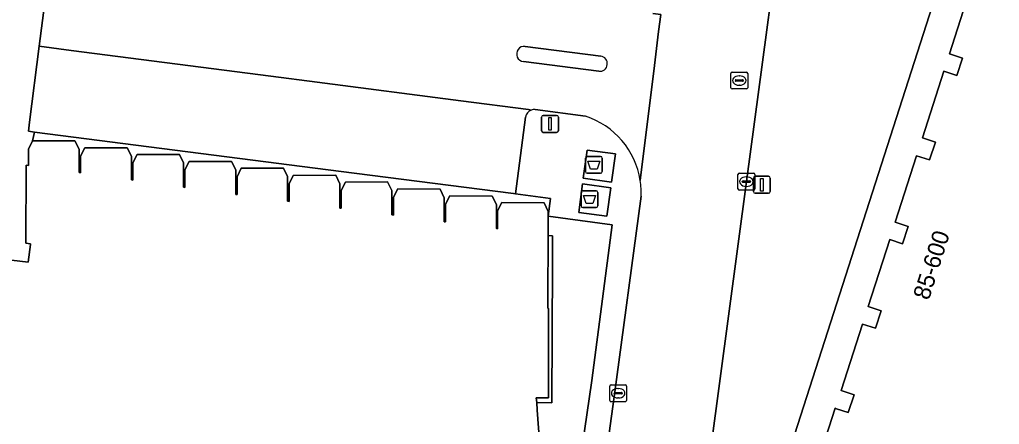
# Model space of a CAD drawing. Extents: x 160675 to 161153, y 383241 to 383714.
# Drawn here: x 160754 to 160812.1, y 383306.8 to 383330.8 of the extents above; entities that cross this region are included whole.
import ezdxf

# ---------------------------------------------------------------- set-up
doc = ezdxf.new("R2010")
doc.units = 0
for name, color, linetype in [('IMGEO_Afval_apart_plaats', 7, 'Continuous'), ('IMGEO_Groenvoorziening', 7, 'Continuous'), ('IMGEO_Kolk', 7, 'Continuous'), ('IMGEO_Lichtmast', 7, 'Continuous'), ('IMGEO_Muur', 7, 'Continuous'), ('IMGEO_Pand', 7, 'Continuous'), ('IMGEO_Pand_nummerreeks', 7, 'Continuous'), ('IMGEO_Parkeervlak_open', 7, 'Continuous'), ('IMGEO_Rijbaan_lokaal_open', 7, 'Continuous'), ('IMGEO_Rioolput', 7, 'Continuous'), ('IMGEO_Verkeerseiland_open', 7, 'Continuous'), ('IMGEO_Voetpad_gesloten', 7, 'Continuous'), ('IMGEO_Voetpad_open', 7, 'Continuous')]:
    doc.layers.add(name, color=color, linetype=linetype)

msp = doc.modelspace()

# ---------------------------------------------------------------- linework, layer by layer
at = {"layer": 'IMGEO_Afval_apart_plaats'}
for p, q in [((160787.535, 383321.83), (160787.535, 383322.63)), ((160787.535, 383322.63), (160787.535, 383321.83)), ((160787.635, 383322.73), (160788.425, 383322.73)), ((160788.425, 383322.73), (160787.635, 383322.73)), ((160788.525, 383322.63), (160788.525, 383321.83)), ((160788.525, 383321.83), (160788.525, 383322.63)), ((160788.425, 383321.73), (160787.635, 383321.73)), ((160787.635, 383321.73), (160788.425, 383321.73)), ((160787.375, 383320.7), (160788.165, 383320.7)), ((160788.165, 383320.7), (160787.375, 383320.7)), ((160787.275, 383319.8), (160787.275, 383320.6)), ((160787.275, 383320.6), (160787.275, 383319.8)), ((160788.265, 383320.6), (160788.265, 383319.8)), ((160788.265, 383319.8), (160788.265, 383320.6)), ((160788.165, 383319.7), (160787.375, 383319.7)), ((160787.375, 383319.7), (160788.165, 383319.7))]:
    msp.add_line(p, q, dxfattribs=at)
for points in [[(160787.678, 383322.444), (160788.382, 383322.444), (160788.233, 383321.974), (160787.827, 383321.974), (160787.678, 383322.444)], [(160787.418, 383320.414), (160788.122, 383320.414), (160787.973, 383319.944), (160787.567, 383319.944), (160787.418, 383320.414)]]:
    msp.add_lwpolyline(points, dxfattribs=at)
for centre, start, end in [((160787.635, 383322.63), 90, 180), ((160787.635, 383322.63), 90, 180), ((160788.425, 383322.63), 0, 90), ((160788.425, 383322.63), 360, 90), ((160787.635, 383321.83), 180, 270), ((160787.635, 383321.83), 180, 270), ((160788.425, 383321.83), 270, 0), ((160788.425, 383321.83), 270, 0), ((160787.375, 383320.6), 90, 180), ((160787.375, 383320.6), 90, 180), ((160788.165, 383320.6), 0, 90), ((160788.165, 383320.6), 360, 90), ((160787.375, 383319.8), 180, 270), ((160787.375, 383319.8), 180, 270), ((160788.165, 383319.8), 270, 0), ((160788.165, 383319.8), 270, 0)]:
    msp.add_arc(centre, 0.1, start, end, dxfattribs=at)
at = {"layer": 'IMGEO_Groenvoorziening'}
for points in [[(160800.391, 383345.424), (160799.695, 383340.873), (160797.071, 383321.237), (160794.447, 383301.572), (160793.115, 383291.71), (160793.033, 383291.064), (160794.963, 383290.783), (160811.629, 383342.72), (160809.925, 383343.284), (160810.812, 383346.001), (160808.782, 383346.694), (160804.384, 383348.108)], [(160786.2, 383297.65), (160787.903, 383309.445), (160789.121, 383318.677), (160785.331, 383319.191), (160785.325, 383318.048), (160785.577, 383318.015), (160785.576, 383317.889), (160785.57, 383316.389), (160785.536, 383308.126), (160784.642, 383308.13), (160784.675, 383307.69), (160784.931, 383304.271)]]:
    msp.add_lwpolyline(points, dxfattribs=at)
msp.add_lwpolyline([(160754.886, 383324.173), (160754.765, 383323.655), (160757.275, 383323.656), (160757.521, 383323.156), (160757.522, 383321.776), (160757.612, 383321.763), (160757.611, 383322.743), (160757.86, 383323.243), (160760.374, 383323.247), (160760.618, 383322.746), (160760.619, 383321.339), (160760.704, 383321.327), (160760.704, 383322.354), (160760.958, 383322.848), (160763.464, 383322.849), (160763.711, 383322.35), (160763.712, 383320.902), (160763.798, 383320.89), (160763.798, 383321.931), (160764.048, 383322.431), (160766.548, 383322.427), (160766.803, 383321.928), (160766.804, 383320.478), (160766.882, 383320.468), (160766.881, 383321.529), (160767.13, 383322.029), (160769.629, 383322.031), (160769.879, 383321.534), (160769.88, 383320.074), (160769.972, 383320.062), (160769.971, 383321.105), (160769.976, 383321.116), (160770.219, 383321.606), (160772.732, 383321.614), (160772.977, 383321.114), (160772.977, 383319.668), (160773.06, 383319.657), (160773.06, 383320.702), (160773.307, 383321.203), (160775.806, 383321.216), (160776.054, 383320.717), (160776.055, 383319.264), (160776.161, 383319.25), (160776.161, 383320.31), (160776.415, 383320.808), (160778.923, 383320.79), (160779.166, 383320.286), (160779.166, 383318.856), (160779.243, 383318.846), (160779.243, 383319.899), (160779.496, 383320.398), (160782.011, 383320.385), (160782.256, 383319.881), (160782.257, 383318.451), (160782.326, 383318.441), (160782.326, 383319.498), (160782.577, 383319.997), (160785.09, 383319.987), (160785.332, 383319.46), (160785.331, 383319.191), (160785.463, 383320.244), (160783.387, 383320.523), (160783.274, 383320.538), (160773.83, 383321.747)], close=True, dxfattribs=at)
at = {"layer": 'IMGEO_Kolk'}
for p, q in [((160796.57, 383320.811), (160796.57, 383321.663)), ((160796.645, 383321.737), (160797.497, 383321.737)), ((160796.872, 383321.28), (160797.27, 383321.28)), ((160797.058, 383321.517), (160797.083, 383321.517)), ((160797.571, 383321.663), (160797.571, 383320.811)), ((160797.497, 383320.737), (160796.645, 383320.737)), ((160796.829, 383321.231), (160796.829, 383321.243)), ((160797.267, 383321.194), (160796.869, 383321.194)), ((160797.081, 383320.957), (160797.056, 383320.957)), ((160797.313, 383321.243), (160797.313, 383321.231)), ((160788.972, 383308.261), (160788.972, 383309.113)), ((160789.047, 383309.187), (160789.899, 383309.187)), ((160789.973, 383309.113), (160789.973, 383308.261)), ((160789.231, 383308.681), (160789.231, 383308.693)), ((160789.669, 383308.644), (160789.271, 383308.644)), ((160789.274, 383308.73), (160789.672, 383308.73)), ((160789.46, 383308.967), (160789.485, 383308.967)), ((160789.715, 383308.693), (160789.715, 383308.681)), ((160789.899, 383308.187), (160789.047, 383308.187)), ((160789.483, 383308.407), (160789.458, 383308.407))]:
    msp.add_line(p, q, dxfattribs=at)
for points in [[(160796.57, 383320.811), (160796.57, 383321.663)], [(160796.645, 383321.737), (160797.497, 383321.737)], [(160797.571, 383321.663), (160797.571, 383320.811)], [(160797.497, 383320.737), (160796.645, 383320.737)], [(160788.972, 383308.261), (160788.972, 383309.113)], [(160789.047, 383309.187), (160789.899, 383309.187)], [(160789.973, 383309.113), (160789.973, 383308.261)], [(160789.899, 383308.187), (160789.047, 383308.187)]]:
    msp.add_lwpolyline(points, dxfattribs=at)
for centre, radius, start, end in [((160796.647, 383321.661), 0.0765, 91.55205, 178.44795), ((160796.647, 383321.661), 0.0765, 91.55205, 178.44795), ((160796.869, 383321.24), 0.0403, 85.87752, 175.75265), ((160797.274, 383321.242), 0.0386, 1.73085, 96.63898), ((160797.495, 383321.661), 0.0765, 1.55205, 88.44795), ((160797.495, 383321.661), 0.0765, 1.55205, 88.44795), ((160796.647, 383320.813), 0.0765, 181.55205, 268.44795), ((160796.647, 383320.813), 0.0765, 181.55205, 268.44795), ((160796.866, 383321.23), 0.0366, 178.93798, 274.71019), ((160797.27, 383321.237), 0.043, 264.86636, 352.45326), ((160797.495, 383320.813), 0.0765, 271.55205, 358.44795), ((160797.495, 383320.813), 0.0765, 271.55205, 358.44795), ((160789.049, 383309.111), 0.0765, 91.55205, 178.44795), ((160789.049, 383309.111), 0.0765, 91.55205, 178.44795), ((160789.897, 383309.111), 0.0765, 1.55205, 88.44795), ((160789.897, 383309.111), 0.0765, 1.55205, 88.44795), ((160789.271, 383308.69), 0.0403, 85.87752, 175.75265), ((160789.268, 383308.68), 0.0366, 178.93798, 274.71019), ((160789.672, 383308.687), 0.043, 264.86636, 352.45326), ((160789.676, 383308.692), 0.0386, 1.73085, 96.63898), ((160789.049, 383308.263), 0.0765, 181.55205, 268.44795), ((160789.049, 383308.263), 0.0765, 181.55205, 268.44795), ((160789.897, 383308.263), 0.0765, 271.55205, 358.44795), ((160789.897, 383308.263), 0.0765, 271.55205, 358.44795)]:
    msp.add_arc(centre, radius, start, end, dxfattribs=at)
for centre, major_axis, ratio, start_param, end_param in [((160797.057, 383321.237), (-0.387, 0.002), 0.722429, 4.712389, 7.853982), ((160797.082, 383321.237), (-0.39, 0.002), 0.717154, 1.570796, 4.712389), ((160789.459, 383308.687), (-0.387, 0.002), 0.722429, 4.712389, 7.853982), ((160789.484, 383308.687), (-0.39, 0.002), 0.717154, 1.570796, 4.712389)]:
    msp.add_ellipse(centre, major_axis=major_axis, ratio=ratio, start_param=start_param, end_param=end_param, dxfattribs=at)
at = {"layer": 'IMGEO_Lichtmast'}
for p, q in [((160784.935, 383324.26), (160784.935, 383325.06)), ((160784.935, 383325.06), (160784.935, 383324.26)), ((160785.035, 383325.16), (160785.825, 383325.16)), ((160785.825, 383325.16), (160785.035, 383325.16)), ((160785.925, 383325.06), (160785.925, 383324.26)), ((160785.925, 383324.26), (160785.925, 383325.06)), ((160785.825, 383324.16), (160785.035, 383324.16)), ((160785.035, 383324.16), (160785.825, 383324.16)), ((160797.491, 383320.653), (160797.491, 383321.453)), ((160797.491, 383321.453), (160797.491, 383320.653)), ((160797.591, 383321.553), (160798.381, 383321.553)), ((160798.381, 383321.553), (160797.591, 383321.553)), ((160798.481, 383321.453), (160798.481, 383320.653)), ((160798.481, 383320.653), (160798.481, 383321.453)), ((160798.381, 383320.553), (160797.591, 383320.553)), ((160797.591, 383320.553), (160798.381, 383320.553))]:
    msp.add_line(p, q, dxfattribs=at)
for points in [[(160785.355, 383325.035), (160785.505, 383325.035), (160785.505, 383324.285), (160785.355, 383324.285), (160785.355, 383325.035)], [(160797.911, 383321.428), (160798.061, 383321.428), (160798.061, 383320.678), (160797.911, 383320.678), (160797.911, 383321.428)]]:
    msp.add_lwpolyline(points, dxfattribs=at)
for centre, start, end in [((160785.035, 383325.06), 90, 180), ((160785.035, 383325.06), 90, 180), ((160785.825, 383325.06), 0, 90), ((160785.825, 383325.06), 360, 90), ((160785.035, 383324.26), 180, 270), ((160785.035, 383324.26), 180, 270), ((160785.825, 383324.26), 270, 0), ((160785.825, 383324.26), 270, 0), ((160797.591, 383321.453), 90, 180), ((160797.591, 383321.453), 90, 180), ((160798.381, 383321.453), 0, 90), ((160798.381, 383321.453), 360, 90), ((160797.591, 383320.653), 180, 270), ((160797.591, 383320.653), 180, 270), ((160798.381, 383320.653), 270, 0), ((160798.381, 383320.653), 270, 0)]:
    msp.add_arc(centre, 0.1, start, end, dxfattribs=at)
at = {"layer": 'IMGEO_Muur'}
msp.add_lwpolyline([(160785.57, 383316.389), (160785.576, 383317.889), (160785.577, 383318.015), (160785.325, 383318.048), (160785.307, 383314.278), (160785.304, 383313.73), (160785.346, 383313.718), (160785.333, 383308.411), (160784.62, 383308.419), (160784.642, 383308.13), (160785.536, 383308.126)], close=True, dxfattribs=at)
at = {"layer": 'IMGEO_Pand'}
for points in [[(160812.507, 383339.449), (160809.099, 383328.814), (160809.87, 383328.567), (160809.547, 383327.538), (160808.776, 383327.786), (160807.505, 383323.835), (160808.276, 383323.587), (160807.93, 383322.528), (160807.159, 383322.776), (160805.888, 383318.832), (160806.658, 383318.584), (160806.332, 383317.554), (160805.562, 383317.803), (160804.281, 383313.834), (160805.052, 383313.585), (160804.718, 383312.546), (160803.946, 383312.793), (160802.682, 383308.844), (160803.453, 383308.597), (160803.105, 383307.552), (160802.409, 383307.77), (160802.332, 383307.794), (160796.79, 383290.554)], [(160784.931, 383304.271), (160784.675, 383307.69), (160784.642, 383308.13), (160784.62, 383308.419), (160785.333, 383308.411), (160785.346, 383313.718), (160785.304, 383313.73), (160785.307, 383314.278), (160785.325, 383318.048), (160785.331, 383319.191), (160785.332, 383319.46), (160785.09, 383319.987), (160782.577, 383319.997), (160782.326, 383319.498), (160782.326, 383318.441), (160782.257, 383318.451), (160782.256, 383319.881), (160782.011, 383320.385), (160779.496, 383320.398), (160779.243, 383319.899), (160779.243, 383318.846), (160779.166, 383318.856), (160779.166, 383320.286), (160778.923, 383320.79), (160776.415, 383320.808), (160776.161, 383320.31), (160776.161, 383319.25), (160776.055, 383319.264), (160776.054, 383320.717), (160775.806, 383321.216), (160773.307, 383321.203), (160773.06, 383320.702), (160773.06, 383319.657), (160772.977, 383319.668), (160772.977, 383321.114), (160772.732, 383321.614), (160770.219, 383321.606), (160769.976, 383321.116), (160769.971, 383321.105), (160769.972, 383320.062), (160769.88, 383320.074), (160769.879, 383321.534), (160769.629, 383322.031), (160767.13, 383322.029), (160766.881, 383321.529), (160766.882, 383320.468), (160766.804, 383320.478), (160766.803, 383321.928), (160766.548, 383322.427), (160764.048, 383322.431), (160763.798, 383321.931), (160763.798, 383320.89), (160763.712, 383320.902), (160763.711, 383322.35), (160763.464, 383322.849), (160760.958, 383322.848), (160760.704, 383322.354), (160760.704, 383321.327), (160760.619, 383321.339), (160760.618, 383322.746), (160760.374, 383323.247), (160757.86, 383323.243), (160757.611, 383322.743), (160757.612, 383321.763), (160757.522, 383321.776), (160757.521, 383323.156), (160757.275, 383323.656), (160754.765, 383323.655), (160754.516, 383323.163), (160754.517, 383322.2), (160754.378, 383322.22), (160754.364, 383317.585), (160754.639, 383317.549), (160754.635, 383317.518), (160754.497, 383316.46), (160752.505, 383316.702)]]:
    msp.add_lwpolyline(points, dxfattribs=at)
at = {"layer": 'IMGEO_Parkeervlak_open'}
for points in [[(160755.161, 383329.27), (160754.584, 383324.767), (160754.514, 383324.221), (160754.886, 383324.173), (160773.83, 383321.747), (160783.274, 383320.538), (160783.387, 383320.523), (160783.971, 383325.062)], [(160784.323, 383325.486), (160784.152, 383325.508), (160780.14, 383326.029), (160771.64, 383327.131), (160768.888, 383327.489), (160757.053, 383329.024), (160755.161, 383329.27)]]:
    msp.add_lwpolyline(points, dxfattribs=at)
msp.add_arc((160784.495, 383324.985), 0.529, 108.92091, 171.68095, dxfattribs=at)
at = {"layer": 'IMGEO_Rijbaan_lokaal_open'}
for points in [[(160790.827, 383320.367), (160789.229, 383308.479), (160787.712, 383297.432), (160787.044, 383292.535), (160793.115, 383291.71), (160794.447, 383301.572), (160797.071, 383321.237), (160799.695, 383340.873), (160800.391, 383345.424)], [(160771.855, 383332.41), (160768.356, 383332.858), (160755.826, 383334.462), (160755.161, 383329.27), (160757.053, 383329.024), (160768.888, 383327.489), (160771.64, 383327.131), (160780.14, 383326.029), (160784.152, 383325.508), (160784.323, 383325.486)], [(160791.53, 383331.202), (160791.995, 383331.154), (160791.869, 383330.134), (160791.621, 383328.132), (160790.776, 383321.303)], [(160790.776, 383321.303), (160791.621, 383328.132), (160791.869, 383330.134), (160791.995, 383331.154), (160791.53, 383331.202)], [(160783.962, 383329.258), (160788.435, 383328.678)], [(160788.327, 383327.783), (160783.854, 383328.354)], [(160784.542, 383325.513), (160787.527, 383325.118)]]:
    msp.add_lwpolyline(points, dxfattribs=at)
for centre, radius, start, end in [((160783.908, 383328.806), 0.455, 83.17215, 263.20228), ((160788.379, 383328.231), 0.451, 263.42798, 82.81075), ((160784.496, 383324.984), 0.531, 85.02728, 109.02951), ((160786.062, 383320.579), 4.77, 8.73041, 72.10756), ((160786.15, 383320.582), 4.682, 357.37329, 8.86432)]:
    msp.add_arc(centre, radius, start, end, dxfattribs=at)
at = {"layer": 'IMGEO_Rioolput'}
for p, q in [((160796.147, 383326.806), (160796.147, 383327.658)), ((160796.222, 383327.732), (160797.074, 383327.732)), ((160797.148, 383327.658), (160797.148, 383326.806)), ((160796.406, 383327.226), (160796.406, 383327.238)), ((160796.844, 383327.189), (160796.446, 383327.189)), ((160796.449, 383327.275), (160796.847, 383327.275)), ((160796.635, 383327.512), (160796.66, 383327.512)), ((160796.89, 383327.238), (160796.89, 383327.226)), ((160797.074, 383326.732), (160796.222, 383326.732)), ((160796.658, 383326.952), (160796.633, 383326.952))]:
    msp.add_line(p, q, dxfattribs=at)
for points in [[(160796.147, 383326.806), (160796.147, 383327.658)], [(160796.222, 383327.732), (160797.074, 383327.732)], [(160797.148, 383327.658), (160797.148, 383326.806)], [(160797.074, 383326.732), (160796.222, 383326.732)]]:
    msp.add_lwpolyline(points, dxfattribs=at)
for centre, radius, start, end in [((160796.224, 383327.656), 0.0765, 91.55205, 178.44795), ((160796.224, 383327.656), 0.0765, 91.55205, 178.44795), ((160797.072, 383327.656), 0.0765, 1.55205, 88.44795), ((160797.072, 383327.656), 0.0765, 1.55205, 88.44795), ((160796.446, 383327.235), 0.0403, 85.87752, 175.75265), ((160796.443, 383327.225), 0.0366, 178.93798, 274.71019), ((160796.847, 383327.232), 0.043, 264.86636, 352.45326), ((160796.851, 383327.237), 0.0386, 1.73085, 96.63898), ((160796.224, 383326.808), 0.0765, 181.55205, 268.44795), ((160796.224, 383326.808), 0.0765, 181.55205, 268.44795), ((160797.072, 383326.808), 0.0765, 271.55205, 358.44795), ((160797.072, 383326.808), 0.0765, 271.55205, 358.44795)]:
    msp.add_arc(centre, radius, start, end, dxfattribs=at)
for centre, major_axis, ratio, start_param, end_param in [((160796.634, 383327.232), (-0.387, 0.002), 0.722429, 4.712389, 7.853982), ((160796.659, 383327.232), (-0.39, 0.002), 0.717154, 1.570796, 4.712389)]:
    msp.add_ellipse(centre, major_axis=major_axis, ratio=ratio, start_param=start_param, end_param=end_param, dxfattribs=at)
at = {"layer": 'IMGEO_Verkeerseiland_open'}
for points in [[(160788.435, 383328.678), (160783.962, 383329.258)], [(160783.854, 383328.354), (160788.327, 383327.783)]]:
    msp.add_lwpolyline(points, dxfattribs=at)
for centre, radius, start, end in [((160783.908, 383328.806), 0.455, 83.17215, 263.20228), ((160788.379, 383328.231), 0.451, 263.42798, 82.81075)]:
    msp.add_arc(centre, radius, start, end, dxfattribs=at)
at = {"layer": 'IMGEO_Voetpad_gesloten'}
for points in [[(160789.306, 383322.884), (160787.627, 383323.111), (160787.401, 383321.439), (160789.08, 383321.212)], [(160789.028, 383320.879), (160787.361, 383321.103), (160787.134, 383319.411), (160788.801, 383319.188)]]:
    msp.add_lwpolyline(points, close=True, dxfattribs=at)
at = {"layer": 'IMGEO_Voetpad_open'}
for points in [[(160812.457, 383345.502), (160810.812, 383346.001), (160809.925, 383343.284), (160811.629, 383342.72), (160794.963, 383290.783)], [(160796.79, 383290.554), (160802.332, 383307.794), (160802.409, 383307.77), (160803.105, 383307.552), (160803.453, 383308.597), (160802.682, 383308.844), (160803.946, 383312.793), (160804.718, 383312.546), (160805.052, 383313.585), (160804.281, 383313.834), (160805.562, 383317.803), (160806.332, 383317.554), (160806.658, 383318.584), (160805.888, 383318.832), (160807.159, 383322.776), (160807.93, 383322.528), (160808.276, 383323.587), (160807.505, 383323.835), (160808.776, 383327.786), (160809.547, 383327.538), (160809.87, 383328.567), (160809.099, 383328.814), (160812.507, 383339.449)], [(160755.161, 383329.27), (160755.826, 383334.462), (160768.356, 383332.858), (160771.855, 383332.41)], [(160752.505, 383316.702), (160754.497, 383316.46), (160754.635, 383317.518), (160754.639, 383317.549), (160754.364, 383317.585), (160754.378, 383322.22), (160754.517, 383322.2), (160754.516, 383323.163), (160754.765, 383323.655), (160754.886, 383324.173), (160754.514, 383324.221), (160754.584, 383324.767), (160755.161, 383329.27)], [(160787.527, 383325.118), (160784.542, 383325.513)], [(160783.971, 383325.062), (160783.387, 383320.523), (160785.463, 383320.244), (160785.331, 383319.191), (160789.121, 383318.677), (160787.903, 383309.445), (160786.2, 383297.65), (160787.712, 383297.432), (160789.229, 383308.479)], [(160789.229, 383308.479), (160790.827, 383320.367)]]:
    msp.add_lwpolyline(points, dxfattribs=at)
for points in [[(160787.401, 383321.439), (160787.627, 383323.111), (160789.306, 383322.884), (160789.08, 383321.212)], [(160787.134, 383319.411), (160787.361, 383321.103), (160789.028, 383320.879), (160788.801, 383319.188)]]:
    msp.add_lwpolyline(points, close=True, dxfattribs=at)
for centre, radius, start, end in [((160784.495, 383324.985), 0.529, 108.92091, 171.68095), ((160784.496, 383324.984), 0.531, 85.02728, 109.02951), ((160786.062, 383320.579), 4.77, 8.73041, 72.10756), ((160786.15, 383320.582), 4.682, 357.37329, 8.86432)]:
    msp.add_arc(centre, radius, start, end, dxfattribs=at)

# ---------------------------------------------------------------- texts
at = {"layer": 'IMGEO_Pand_nummerreeks'}
msp.add_text('85-600', height=1, rotation=72.43905, dxfattribs=at).set_placement((160807.881, 383314.162))

doc.saveas('drawing.dxf')
